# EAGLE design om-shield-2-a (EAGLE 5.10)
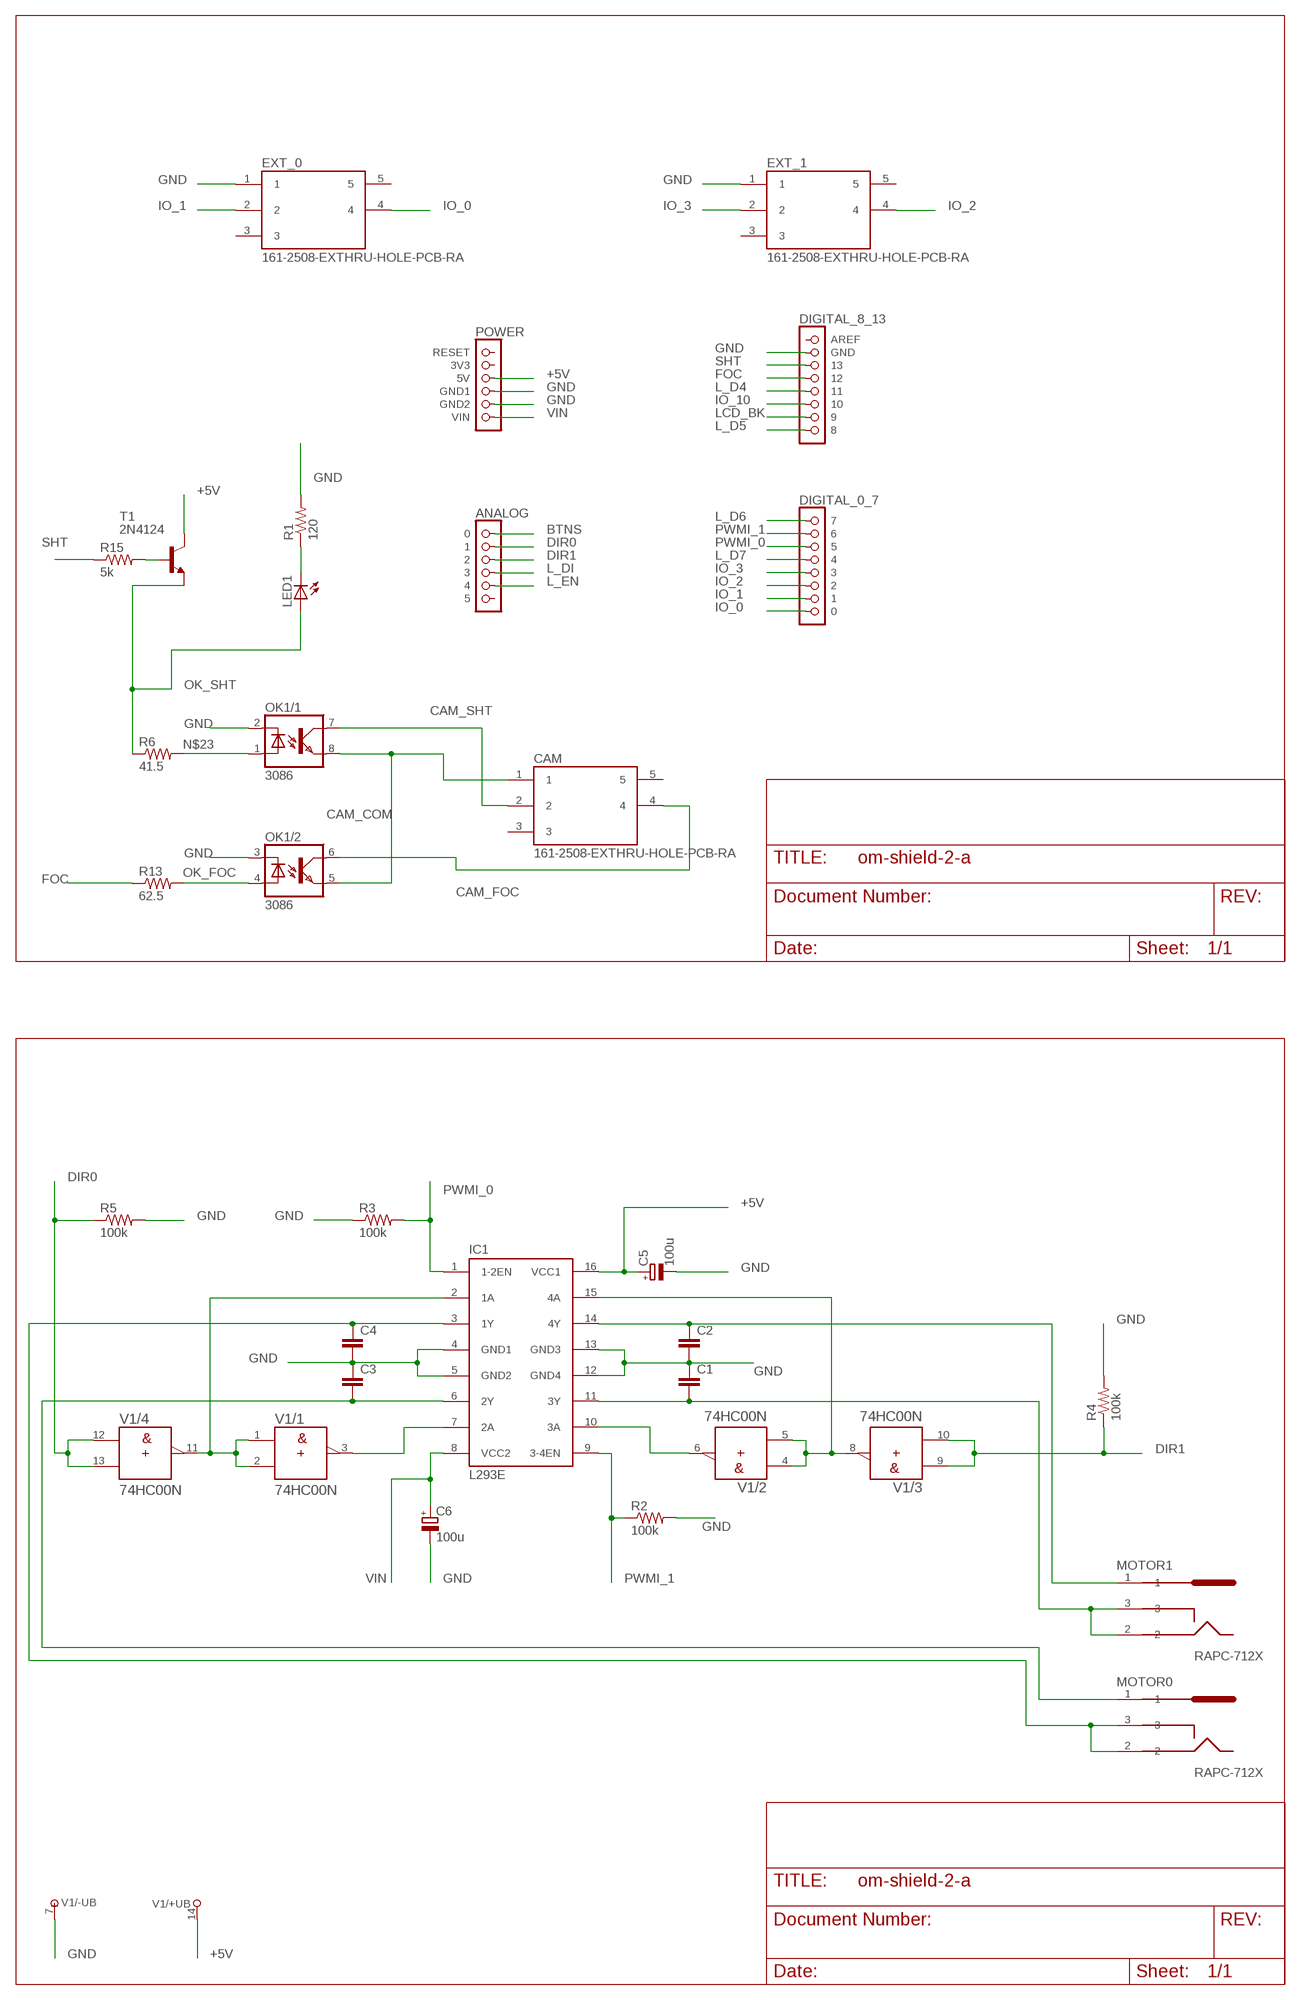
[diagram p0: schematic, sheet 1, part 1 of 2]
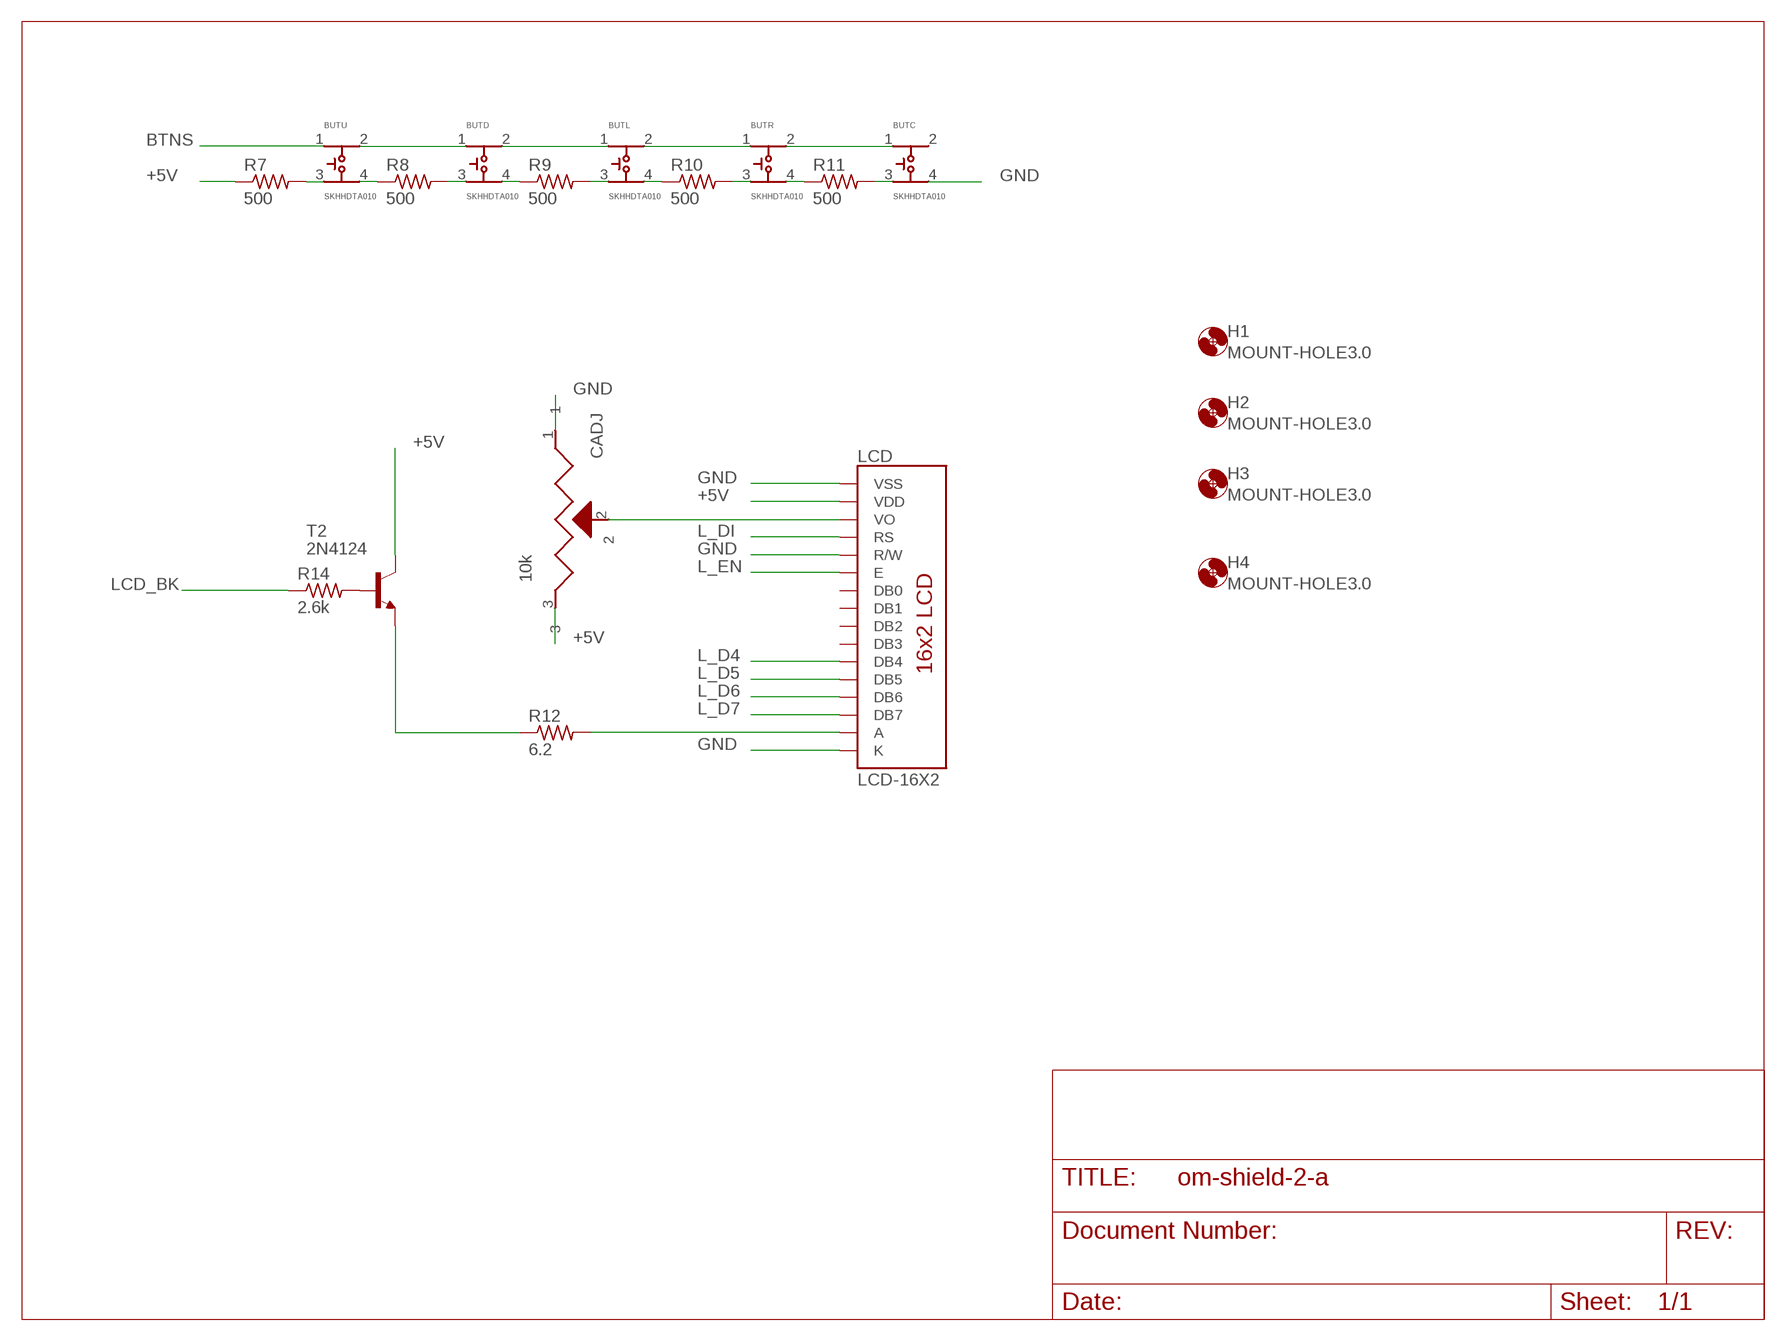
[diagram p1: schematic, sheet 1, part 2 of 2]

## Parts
BUTC  SKHHDTA010  SKHH  [SKHH]
BUTD  SKHHDTA010  SKHH  [SKHH]
BUTL  SKHHDTA010  SKHH  [SKHH]
BUTR  SKHHDTA010  SKHH  [SKHH]
BUTU  SKHHDTA010  SKHH  [SKHH]
C1  C5/3  [C5B3]
C2  C5/3  [C5B3]
C3  C5/3  [C5B3]
C4  C5/3  [C5B3]
C5  100u  CPOL-EUE2-5  [E2-5]
C6  100u  CPOL-EUE2-5  [E2-5]
CADJ  10k  3362U  [3362W]
CAM  161-2508-EXTHRU-HOLE-PCB-RA  [PCB-HORIZ]
EXT_0  161-2508-EXTHRU-HOLE-PCB-RA  [PCB-HORIZ]
EXT_1  161-2508-EXTHRU-HOLE-PCB-RA  [PCB-HORIZ]
H1  MOUNT-HOLE3.0  [3,0]
H2  MOUNT-HOLE3.0  [3,0]
H3  MOUNT-HOLE3.0  [3,0]
H4  MOUNT-HOLE3.0  [3,0]
IC1  L293E  [DIL16]
LCD  LCD-16X2  [LCD-16X2]
LED1  LED3MM  [LED3MM]
MOTOR0  RAPC-712X  [RAPC712X]
MOTOR1  RAPC-712X  [RAPC712X]
OK1  3086  [DIL08]
R1  120  R-US_0207/7  [0207/7]
R2  100k  R-US_0207/7  [0207/7]
R3  100k  R-US_0207/7  [0207/7]
R4  100k  R-US_0207/7  [0207/7]
R5  100k  R-US_0207/7  [0207/7]
R6  41.5  R-US_0207/7  [0207/7]
R7  500  R-US_0207/7  [0207/7]
R8  500  R-US_0207/7  [0207/7]
R9  500  R-US_0207/7  [0207/7]
R10  500  R-US_0207/7  [0207/7]
R11  500  R-US_0207/7  [0207/7]
R12  6.2  R-US_0207/7  [0207/7]
R13  62.5  R-US_0207/7  [0207/7]
R14  2.6k  R-US_0207/7  [0207/7]
R15  5k  R-US_0207/7  [0207/7]
T1  2N4124  2N4124-NPN-TO92-CBE  [TO92-CBE]
T2  2N4124  2N4124-NPN-TO92-CBE  [TO92-CBE]
U$1  POWER  [1X06]
U$2  ANALOG  [1X06]
U$3  DIGITAL_0_7  [1X08]
U$4  DIGITAL_8_13  [1X08]
V1  74HC00N  [DIL14]

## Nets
+5V: C5.+ CADJ.3 IC1.16(VCC1) LCD.2(VDD) R7.1 T1.C T2.C U$1.3(5V) V1.14(/+UB:+UB)
BTNS: BUTU.1 U$2.1
CAM_COM: CAM.1 OK1.5(/2:EMI) OK1.8(/1:EMI)
CAM_FOC: CAM.4 OK1.6(/2:COL)
CAM_SHT: CAM.2 OK1.7(/1:COL)
DIR0: R5.1 U$2.2 V1.12(/4:A) V1.13(/4:B)
DIR1: R4.1 U$2.3 V1.9(/3:A) V1.10(/3:B)
FOC: R13.1 U$4.4
GND: BUTC.4 C1.1 C2.2 C3.1 C4.2 C5.- C6.- CADJ.1 EXT_0.1 EXT_1.1 IC1.4(GND1) IC1.5(GND2) IC1.12(GND4) IC1.13(GND3) LCD.1(VSS) LCD.5(R/W) LCD.16(K) OK1.2(/1:C) OK1.3(/2:C) R1.2 R2.2 R3.1 R4.2 R5.2 U$1.4(GND1) U$1.5(GND2) U$4.2(GND) V1.7(/-UB:-UB)
IO_0: EXT_0.4 U$3.8
IO_1: EXT_0.2 U$3.7
IO_2: EXT_1.4 U$3.6
IO_3: EXT_1.2 U$3.5
IO_10: U$4.6
L_D4: LCD.11(DB4) U$4.5
L_D5: LCD.12(DB5) U$4.8
L_D6: LCD.13(DB6) U$3.1
L_D7: LCD.14(DB7) U$3.4
L_DI: LCD.4(RS) U$2.4
L_EN: LCD.6(E) U$2.5
LCD_BK: R14.1 U$4.7
LCDA: LCD.15(A) R12.2
M0_A: C3.2 IC1.6(2Y) MOTOR0.1
M0_B: C4.1 IC1.3(1Y) MOTOR0.2 MOTOR0.3
M1_A: C2.1 IC1.14(4Y) MOTOR1.1
M1_B: C1.2 IC1.11(3Y) MOTOR1.2 MOTOR1.3
N$1: LED1.K(C) R1.1
N$2: IC1.7(2A) V1.3(/1:Y)
N$3: IC1.2(1A) V1.1(/1:A) V1.2(/1:B) V1.11(/4:Y)
N$4: IC1.10(3A) V1.6(/2:Y)
N$5: IC1.15(4A) V1.4(/2:A) V1.5(/2:B) V1.8(/3:Y)
N$8: BUTU.3 R7.2
N$9: BUTU.4 R8.1
N$10: BUTD.3 R8.2
N$11: BUTD.4 R9.1
N$12: BUTL.3 R9.2
N$13: BUTL.4 R10.1
N$14: BUTR.3 R10.2
N$15: BUTR.4 R11.1
N$16: BUTC.3 R11.2
N$17: BUTD.1 BUTU.2
N$18: BUTD.2 BUTL.1
N$19: BUTL.2 BUTR.1
N$20: BUTC.1 BUTR.2
N$21: CADJ.2 LCD.3(VO)
N$23: OK1.1(/1:A) R6.2
N$24: R12.1 T2.E
N$25: R15.2 T1.B
N$26: R14.2 T2.B
OK_FOC: OK1.4(/2:A) R13.2
OK_SHT: LED1.A R6.1 T1.E
PWMI_0: IC1.1(1-2EN) R3.2 U$3.3
PWMI_1: IC1.9(3-4EN) R2.1 U$3.2
SHT: R15.1 U$4.3
VIN: C6.+ IC1.8(VCC2) U$1.6(VIN)
Unconnected: BUTC.2 CAM.3 CAM.5 EXT_0.3 EXT_0.5 EXT_1.3 EXT_1.5 LCD.7(DB0) LCD.8(DB1) LCD.9(DB2) LCD.10(DB3) U$1.1(RESET) U$1.2(3V3) U$2.6 U$4.1(AREF)

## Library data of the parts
BUTC BUTD BUTL BUTR BUTU = alps:SKHH: SKHH* vertical/joint stem momentary pushbutton PCB mount switch
C1-C4 = capacitor-wima:C: CAPACITOR
C5 C6 = rcl:CPOL-EU: POLARIZED CAPACITOR, European symbol
CADJ = bourns:3362U: Bourns 3362U trim pot top-adjust.
CAM EXT_0 EXT_1 = kobiconn-161-2508-ex:161-2508-EX
H1-H4 = holes:MOUNT-HOLE: MOUNTING HOLE with drill center marker
IC1 = texas:L293E: TI DEVICE
LCD = SparkFun:LCD-16X2
LED1 = SparkFun:LED: LEDs
MOTOR0 MOTOR1 = switchcraft:RAPC-712X
OK1 = cchurch-optocoupler:3086: NTE3086 Dual Opto-Coupler DIL8
R1-R15 = resistor:R-US_: RESISTOR, American symbol
T1 T2 = transistor:*-NPN-: NPN Transistror BF959 corrected 2008.03.06
U$1 = arduino:POWER
U$2 = arduino:ANALOG
U$3 = arduino:DIGITAL_0_7
U$4 = arduino:DIGITAL_8_13
V1 = 74ttl-din:74*00: Quad 2-input NAND gate

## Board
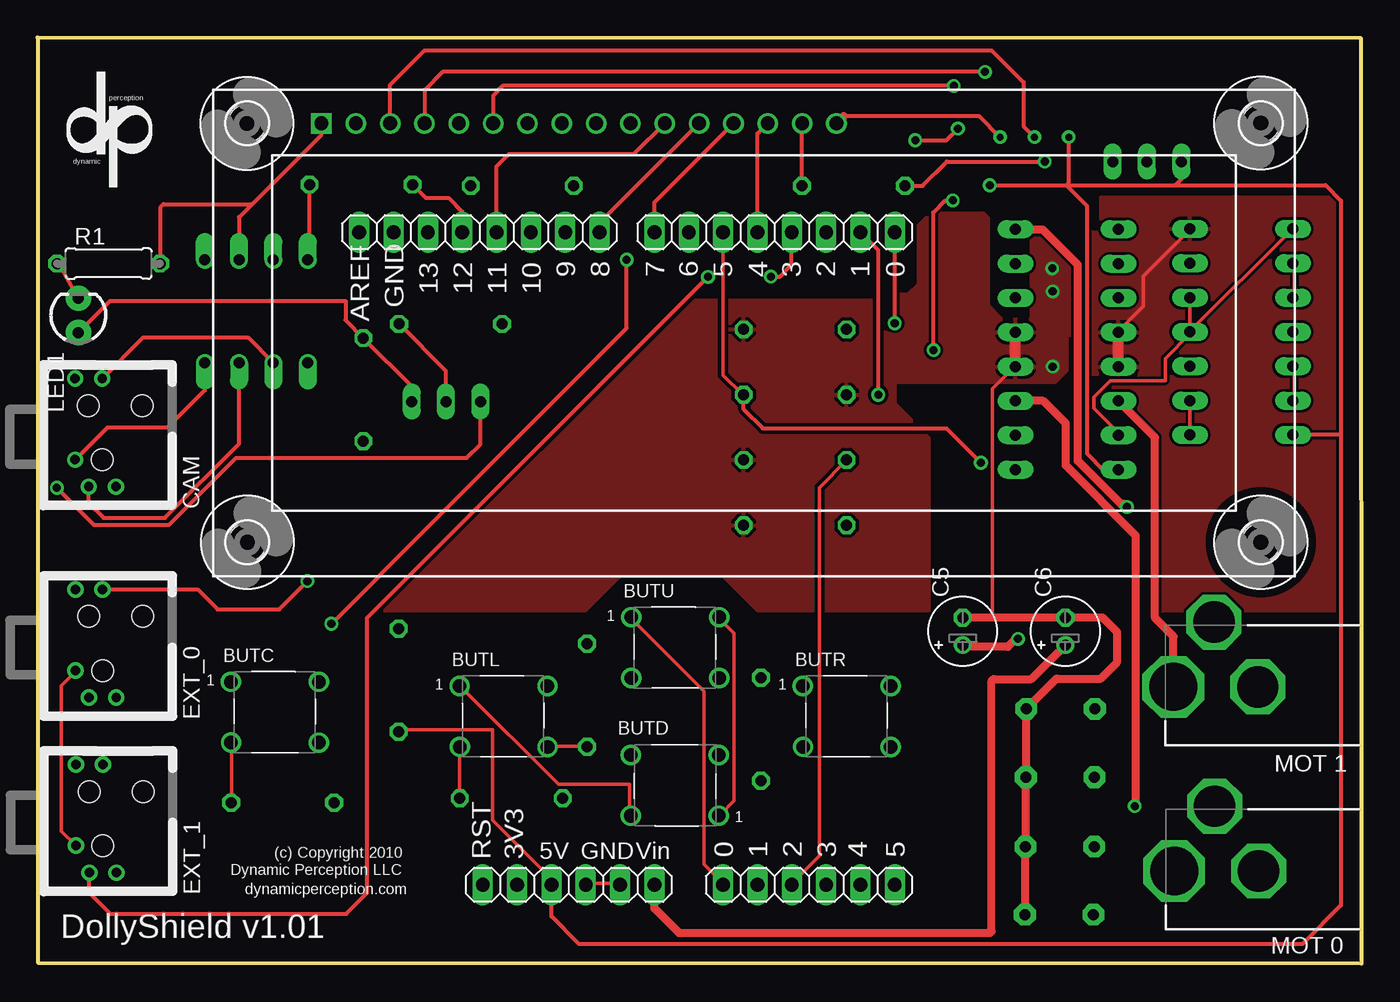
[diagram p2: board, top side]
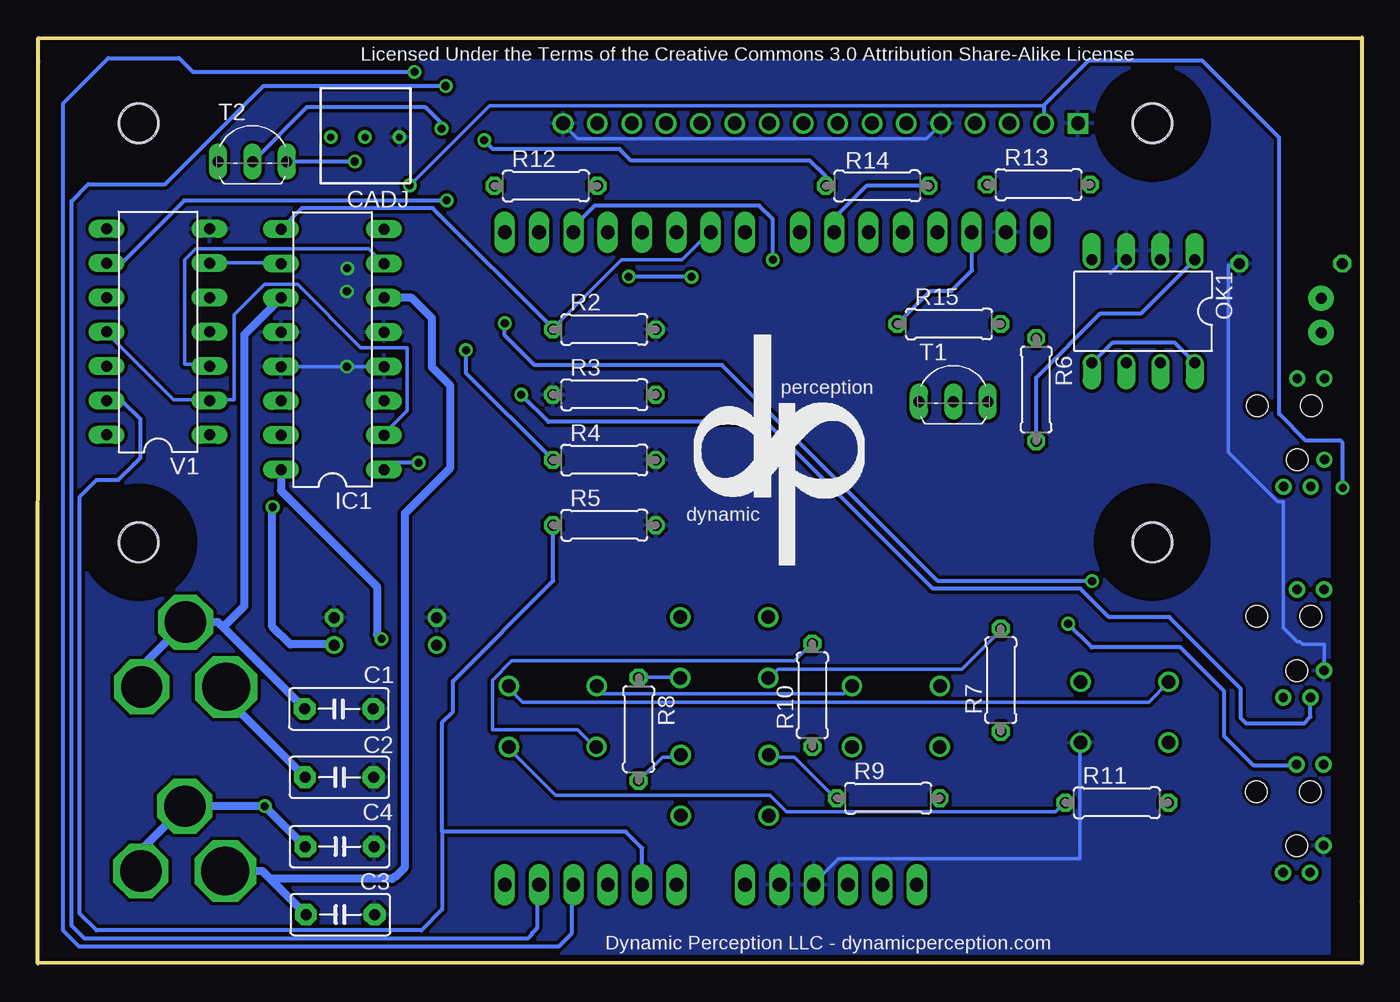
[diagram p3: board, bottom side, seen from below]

Size 98.04 x 68.48 mm. Coordinates in mm from the lower left corner, seen from the top.
Outline: 0,3.28 0,56.62
Outline: 0.08,68.48 0.1,0.05 98.04,0 98.02,68.43 0.08,68.48
Copper layers (1*16): Top 0.035mm / dielectric 1.5mm / Bottom 0.035mm
Design rules "default *": minimum track width 10mil, minimum drill 24mil, track to track 8mil, track to pad 8mil, pad to pad 8mil, via to via 8mil, smd to smd 8mil, copper to edge 10mil, drill to drill 8mil, minimum pad ring 10mil, minimum via ring 8mil, stop-mask expansion 4mil, vias tented up to drill 0mil, thermal gap 10mil

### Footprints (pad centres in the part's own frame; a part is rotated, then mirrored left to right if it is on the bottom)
SKHH = drill 1 round: 1 -3.242,2.261; 2 3.264,2.262; 3 -3.23,-2.242; 4 3.267,-2.245
C5B3 = drill 0.813 pad 1.6 octagon: 1 -2.54,0; 2 2.54,0
E2-5 = drill 0.813 pad 1.27 round: + -1.016,0 | drill 0.813 pad 1.27 octagon: - 1.016,0
3362W = drill 0.5 round: 1 -2.565,0.076; 2 -0.025,0.076; 3 2.515,0.076
PCB-HORIZ = drill 0.7 round: 1 -1.96,-0.32; 2 -3.96,-1.32; 3 -3.96,-3.33; 4 4.04,-2.32; 5 4.04,-0.32 | hole 1.6: 2.04,-1.29; 2.04,-5.29; -1.96,-2.32
3,0 = hole 3: 0,0
DIL16 = drill 0.813 long: 1 -8.89,-3.81; 2 -6.35,-3.81; 3 -3.81,-3.81; 4 -1.27,-3.81; 5 1.27,-3.81; 6 3.81,-3.81; 7 6.35,-3.81; 8 8.89,-3.81; 9 8.89,3.81; 10 6.35,3.81; 11 3.81,3.81; 12 1.27,3.81; 13 -1.27,3.81; 14 -3.81,3.81; 15 -6.35,3.81; 16 -8.89,3.81
LCD-16X2 = drill 1.016 square: 1 -32,15.5 | drill 1.016 round: 2 -29.46,15.5; 3 -26.92,15.5; 4 -24.38,15.5; 5 -21.84,15.5; 6 -19.3,15.5; 7 -16.76,15.5; 8 -14.22,15.5; 9 -11.68,15.5; 10 -9.14,15.5; 11 -6.6,15.5; 12 -4.06,15.5; 13 -1.52,15.5; 14 1.02,15.5; 15 3.56,15.5; 16 6.1,15.5 | hole 2.8: -37.5,15.5; -37.5,-15.5; 37.5,15.5; 37.5,-15.5
LED3MM = drill 0.813 pad 1.88 round: A -1.27,0; K 1.27,0
RAPC712X = drill 3.556 octagon: 1 0,-6.248 | drill 3.048 octagon: 2 0,0; 3 -4.801,-3.251
DIL08 = drill 0.813 offset: 1 -3.81,-3.81; 2 -1.27,-3.81; 3 1.27,-3.81; 4 3.81,-3.81; 5 3.81,3.81; 6 1.27,3.81; 7 -1.27,3.81; 8 -3.81,3.81
0207/7 = drill 0.813 octagon: 1 -3.81,0; 2 3.81,0
TO92-CBE = drill 0.813 long: B 0,0; C -2.54,0; E 2.54,0
1X06 = drill 1.016 long: 1 -6.35,0; 2 -3.81,0; 3 -1.27,0; 4 1.27,0; 5 3.81,0; 6 6.35,0
1X08 = drill 1.016 long: 1 -8.89,0; 2 -6.35,0; 3 -3.81,0; 4 -1.27,0; 5 1.27,0; 6 3.81,0; 7 6.35,0; 8 8.89,0
DIL14 = drill 0.813 long: 1 -7.62,-3.81; 2 -5.08,-3.81; 3 -2.54,-3.81; 4 0,-3.81; 5 2.54,-3.81; 6 5.08,-3.81; 7 7.62,-3.81; 8 7.62,3.81; 9 5.08,3.81; 10 2.54,3.81; 11 0,3.81; 12 -2.54,3.81; 13 -5.08,3.81; 14 -7.62,3.81

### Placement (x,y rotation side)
BUTC  17.63,18.57 0 top
BUTD  47.24,13.18 180 top
BUTL  34.54,18.26 0 top
BUTR  59.94,18.26 0 top
BUTU  47.24,23.34 0 top
C1  75.77,18.82 180 bottom
C2  75.74,13.77 0 bottom
C3  75.67,3.61 180 bottom
C4  75.72,8.64 0 bottom
C5  68.53,24.56 90 top
C6  76.12,24.56 90 top
CADJ  73.86,61.19 180 bottom
CAM  2.54,39.22 90 top
EXT_0  2.57,23.62 90 top
EXT_1  2.59,10.67 90 top
H1  15.57,62.13 0 top
H2  90.58,62.15 0 top
H3  15.6,31.14 0 top
H4  90.58,31.14 0 top
IC1  76.25,45.42 90 bottom
LCD  53.09,46.63 0 top
LED1  3.1,47.93 90 top
MOTOR0  90.42,6.83 270 top
MOTOR1  90.37,20.45 270 top
OK1  16.26,48.23 180 bottom
R1  5.33,51.77 0 top
R2  56.13,46.89 0 bottom
R3  56.13,42.06 0 bottom
R4  56.13,37.24 0 bottom
R5  56.13,32.41 0 bottom
R6  24.18,42.44 270 bottom
R7  26.8,20.95 90 bottom
R8  53.59,17.32 270 bottom
R9  35.13,12.22 0 bottom
R10  40.74,19.84 90 bottom
R11  18.21,11.89 0 bottom
R12  60.45,57.51 0 bottom
R13  24,57.61 0 bottom
R14  35.94,57.51 180 bottom
R15  30.63,47.29 0 bottom
T1  30.3,41.55 0 bottom
T2  82.17,59.31 0 bottom
U$1  39.37,5.82 0 top
U$2  57.15,5.82 0 top
U$3  54.61,54.08 0 top
U$4  32.77,54.08 0 top
V1  89.15,46.71 90 bottom

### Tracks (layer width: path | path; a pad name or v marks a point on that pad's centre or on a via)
+5V  (via drill 0.6)
  Top 0.254: R7.1 26.82,17.3 33.73,17.3 33.73,10.59 38,6.32 38,5.92 U$1.3
  Top 0.305: 84.25,57.56 95.38,57.56 96.52,56.41 96.52,39.09 | 76.2,57.56 84.25,57.56 | v70.54,57.56 76.2,57.56 | U$1.3 38.1,3.48 40.16,1.42 93.65,1.42 96.52,4.29 96.52,39.09 | CADJ.3 76.38,57.73 76.2,57.56 | T2.C 84.71,58.01 84.25,57.56 | 96.52,39.09 V1.14 | IC1.16 78.92,36.53 77.72,37.72 77.72,56.03 76.2,57.56 | T1.C 32.84,38.4 31.83,37.39 14.76,37.39 9.8,32.44 4.24,32.44 v1.5,35.18
  Top 0.61: C5.+ 68.66,23.42 71.88,23.42 72.47,24 v72.62,24
  Bottom 0.254: 70.31,57.73 64.62,63.42 23.77,63.42 23.63,63.47
  Bottom 0.305: LCD.2 23.63,63.47 20.32,66.78 11.89,66.78 6.2,61.09 6.2,40.64 4.22,38.66 1.65,38.66 1.5,38.51 1.5,36.3 v1.5,35.18 | v70.54,57.56 70.48,57.56 70.31,57.73
  Bottom 0.61: v72.62,24 72.95,24.33 72.95,27.86 80.06,34.98 IC1.16
BTNS
  Top 0.254: BUTU.1 44.09,25.43 49.38,20.14 49.38,7.34 50.8,5.92 U$2.1
CAM_COM
  Top 0.305: CAM.1 5.25,39.65 9.7,39.65 12.45,42.39 OK1.8
  Bottom 0.305: OK1.8 13.92,45.9 18.54,45.9 20.02,44.42 OK1.5
CAM_FOC
  Top 0.305: CAM.4 7.91,46.3 15.65,46.3 OK1.6
CAM_SHT
  Top 0.305: CAM.2 3.86,34.04 4.95,32.94 9.5,32.94 14.99,38.43 OK1.7
DIR0
  Top 0.254: V1.13 93.07,41.68 93.07,44.12 V1.12
  Bottom 0.305: V1.13 91.85,41.63 90.45,40.23 90.45,37.39 90.91,36.93 90.93,36.93 92.1,35.76 93.7,35.76 94.94,34.52 94.94,3.68 93.7,2.44 69.67,2.44 68.12,3.99 68.12,9.75 | 68.12,9.75 68.12,17.83 67.33,18.62 67.33,20.88 59.92,28.3 59.92,32.38 R5.1 | U$2.2 53.34,8.53 54.56,9.75 68.12,9.75
DIR1  (via drill 0.6)
  Top 0.254: V1.10 93.07,49.4 93.07,51.64 V1.9 | R4.1 59.94,37.21 57.91,35.18 57.91,7.95 55.88,5.92 U$2.3
  Top 0.305: v66.37,45.36 66.34,45.39 66.34,55.52 67.26,56.44 v67.79,56.44
  Bottom 0.305: R4.1 66.37,43.66 v66.37,45.36 | v67.79,56.44 67.82,56.41 87.22,56.41 91.85,51.79 V1.9
FOC
  Top 0.305: U$4.4 31.5,55.6 30.48,56.62 28.8,56.62 R13.1
GND  (via drill 0.6)
  Top 0.254: U$1.5 43.08,5.92 40.64,5.92 U$1.4 | 72.54,44.32 IC1.4 72.34,44.12 70.71,42.49 70.71,25.58 | 72.54,46.56 IC1.5 72.34,46.76 | V1.7 85.34,54.28 81.89,50.83 81.89,48.59 80.06,46.76 IC1.12 | EXT_0.1 2.85,21.56 1.83,20.55 1.83,9.78 2.85,8.76 EXT_1.1
  Top 0.305: R1.2 9.2,51.82 9.2,55.98 9.37,56.16 15.95,56.16 | OK1.2 14.99,55.19 15.95,56.16 | 15.95,56.16 21.09,61.29 LCD.1 | 59.74,62.69 69.72,62.69 CADJ.1
  Top 0.61: C3.1 73.18,3.66 C4.2 73.2,8.66 C2.2 73.23,13.79 C1.1 75.46,21.06 78.74,21.06 79.96,22.28 79.96,24.51 78.89,25.58 C6.- 70.71,25.58 C5.- | LCD.16 59.74,62.69
  Top 0.813: 72.54,44.32 72.44,44.42 IC1.5 | IC1.13 IC1.12
  Bottom 0.254: BUTC.4 20.93,16.28 20.93,7.75 38.81,7.75 40.64,5.92 U$1.4 | IC1.4 72.54,44.12 80.06,44.12 IC1.13 | LCD.5 31.29,62 32.31,60.99 58.12,60.99 59.13,62 LCD.16 | EXT_0.1 2.85,21.77 2.85,23.6 4.47,23.6 4.67,23.8 4.88,23.8 5.89,24.82 5.89,34.16 6.3,34.16 9.96,37.82 9.96,51.64 9.14,51.64 R1.2 | 18.69,51.03 17.68,52.04 OK1.3
  other vias: 75.16,51.41 75.18,49.71 75.18,44.15
  pour Top: 78.13,47.88 83.16,47.88 83.16,43.59 78.13,43.59
  pour Top: 76.2,49 76.2,43.92 76.2,43.84 75.36,43 63.73,43 63.07,43.66 63.07,49.4 63.14,49.48 64.52,49.48 65.28,50.24 65.28,54.58 66.19,55.5 70.05,55.5 70.38,55.17 70.38,48.67 71.4,47.65 74.85,47.65
  pour Bottom (isolate 0.254): 2.54,66.78 2.54,0.74 96.52,0.74 96.52,66.78
  pour Top (isolate 0.254): 63.5,49 27.94,49 22.86,43.92 22.86,26.14 40.64,26.14 43.18,28.68 50.8,28.68 53.34,26.14 66.04,26.14 66.04,38.84 63.5,41.38
  pour Top: 78.74,56.62 78.74,26.14 96.52,26.14 96.52,56.62
  pour Top: 73.66,46.46 73.66,54.08 78.74,54.08 78.74,46.46
IO_0  (via drill 0.6)
  Top 0.305: EXT_0.4 11.91,27.66 13.39,26.19 17.96,26.19 v20.04,28.27 | v63.5,47.35 U$3.8
  Bottom 0.305: v20.04,28.27 31.45,28.27 47.42,44.25 61.29,44.25 63.5,46.46 v63.5,47.35
IO_1  (via drill 0.6)
  Top 0.305: v62.28,42.06 62.28,52.76 U$3.7
  Bottom 0.305: EXT_0.2 3.88,18.24 4.39,17.73 8.64,17.73 9.04,18.14 9.04,20.32 14.33,25.6 18.8,25.6 20.9,27.71 31.83,27.71 44.17,40.06 60.27,40.06 v62.28,42.06
IO_2  (via drill 0.6)
  Top 0.305: v21.82,25.12 25.38,28.68 25.38,28.7 43.66,46.99 v43.66,52.04
  Bottom 0.305: v21.82,25.12 20.07,23.37 13.51,23.37 10.26,20.12 10.26,16.81 8.08,14.63 4.99,14.63 EXT_1.4 | v43.66,52.04 43.66,55.04 44.68,56.06 56.84,56.06 58.45,54.46 58.45,54.1 U$3.6
IO_3  (via drill 0.6)
  Top 0.305: EXT_1.2 3.91,5.21 5.46,3.66 22.91,3.66 24.46,5.21 24.46,25.55 v49.68,50.77 | v54.33,50.8 54.99,50.8 55.85,51.66 55.85,54.05 U$3.5
  Bottom 0.305: v49.68,50.77 54.3,50.77 v54.33,50.8
L_D4
  Top 0.305: U$4.5 34.04,58.95 34.95,59.87 44.22,59.87 LCD.11
L_D5
  Top 0.305: LCD.12 41.66,54.76 U$4.8
L_D6
  Top 0.305: LCD.13 45.72,56.29 U$3.1
L_D7
  Top 0.305: LCD.14 53.34,61.37 U$3.4
L_DI  (via drill 0.6)
  Top 0.305: LCD.4 28.71,64.6 30.05,65.94 v70.18,65.94
  Bottom 0.305: U$2.4 58.57,5.66 58.57,2.18 59.51,1.24 95,1.24 96.16,2.41 96.16,63.63 92.84,66.95 87.61,66.95 86.59,65.94 v70.18,65.94
L_EN  (via drill 0.6)
  Top 0.305: LCD.6 33.79,64.21 33.78,64.21 33.81,64.21 34.49,64.9 v67.87,64.9
  Bottom 0.305: U$2.5 61.11,5.66 61.11,2.62 61.49,2.24 61.49,2.16 61.82,1.83 94.59,1.83 95.56,2.79 95.56,56.39 94.31,57.63 88.62,57.63 81.36,64.9 v67.87,64.9
LCD_BK
  Bottom 0.305: U$4.7 39.12,55.14 36.75,57.51 R14.1
LCDA
  Top 0.305: R12.2 LCD.15
M0_A
  Bottom 0.61: 80.85,6.25 C3.2 | MOTOR0.1 81.43,6.83 80.85,6.25 | 80.85,6.25 71.83,6.25 71.7,6.38 71.63,6.38 70.89,7.11 70.89,33.3 67.51,36.68 67.51,42.72 68.89,44.09 68.89,47.73 70.38,49.23 IC1.6
M0_B  (via drill 0.6)
  Top 0.61: v81.25,11.63 81.33,11.71 81.33,31.65 76.15,36.83 76.15,39.95 74.5,41.61 IC1.3
  Bottom 0.61: C4.1 v81.25,11.63 MOTOR0.3 90.42,8.38 MOTOR0.2
M1_A
  Top 0.61: IC1.14 82.75,38.91 82.75,25.55 84.12,24.18 MOTOR1.1
  Bottom 0.61: C2.1 84.12,19.61 MOTOR1.1
M1_B
  Bottom 0.61: C1.2 84.53,25.04 | 84.53,25.04 84.73,25.25 MOTOR1.3 90.37,22 MOTOR1.2 | IC1.11 82.75,46.53 82.75,26.44 84.15,25.04 84.53,25.04
N$1
  Top 0.305: R1.1 1.83,51.46 LED1.K
N$2
  Bottom 0.254: IC1.7 72.54,51.84 73.56,52.86 86.36,52.86 87.17,52.04 87.17,44.32 85.34,44.32 V1.3
N$3
  Top 0.254: V1.2 V1.1
  Bottom 0.254: 85.34,41.68 83.52,41.68 83.52,47.98 81.28,50.22 78.84,50.22 74.17,45.54 70.71,45.54 70.71,40.87 72.34,39.24 IC1.2 | 85.34,41.68 87.99,41.68 92.86,46.56 V1.11 | 85.34,41.68 V1.2
N$4
  Bottom 0.254: IC1.10 80.06,51.84 85.34,51.84 V1.6
N$5
  Top 0.254: IC1.15 80.06,39.24 78.23,41.07 78.23,41.88 79.45,43.1 83.52,43.1 83.52,44.73 85.34,46.56 V1.4 85.34,46.76 | 85.34,46.76 V1.5 | 85.34,46.76 92.86,54.28 V1.8
N$6
  Bottom 0.305: 0.1,4.57 0.1,-0.03
N$7
  Bottom 0.305: 98.02,68.45 98.02,66.73 98.04,66.73
N$8
  Bottom 0.254: R7.2 26.82,24.61 29.67,21.77 43.28,21.77 43.89,21.16 BUTU.3
N$9
  Bottom 0.254: R8.1 53.44,21.16 50.6,21.16 BUTU.4
N$10
  Bottom 0.254: R8.2 53.44,13.64 51.82,15.27 50.6,15.27 BUTD.3
N$11
  Bottom 0.254: R9.1 39.01,12.22 42.06,15.27 43.89,15.27 BUTD.4
N$12
  Top 0.254: R9.2 31.29,12.22 31.29,15.87 BUTL.3
N$13
  Top 0.254: R10.1 40.64,16.08 38,16.08 BUTL.4
N$14
  Bottom 0.254: R10.2 40.84,23.6 42.06,22.38 62.99,22.38 64.41,20.95 64.41,17.3 58.12,17.3 56.9,16.08 BUTR.3
N$15
  Bottom 0.254: R11.1 22.15,11.81 22.76,11.2 42.67,11.2 43.89,12.42 59.74,12.42 63.2,15.87 BUTR.4
N$16
  Top 0.254: R11.2 14.43,12.01 14.43,16.28 BUTC.3
N$17
  Top 0.254: BUTD.1 50.6,11 51.61,12.01 51.61,24.41 50.6,25.43 BUTU.2
N$18
  Top 0.254: BUTL.1 31.5,20.35 38.61,13.23 43.89,13.23 43.89,11 BUTD.2
N$19
  Bottom 0.254: BUTR.1 56.69,20.35 56.29,19.94 38.41,19.94 38,20.35 BUTL.2
N$20
  Bottom 0.254: BUTC.1 14.43,20.75 15.85,19.33 62.18,19.33 63.2,20.35 BUTR.2
N$21
  Top 0.305: LCD.3 26.17,65 28.7,67.54 70.66,67.54 73.03,65.18 73.03,61.93 CADJ.2
N$23
  Bottom 0.305: R6.2 24.18,43.33 19.43,48.08 16.41,48.08 OK1.1
N$24  (via drill 0.6)
  Top 0.305: v74.6,59.31 67.36,59.31 65.56,57.51 R12.1
  Bottom 0.305: v74.6,59.31 T2.E
N$25
  Top 0.305: T1.B 30.3,43.81 R15.2
N$26  (via drill 0.6)
  Top 0.305: v65.02,60.88 67.31,60.88 v68.17,61.75
  Bottom 0.305: v65.02,60.88 64.36,60.22 54.99,60.22 54.15,59.39 40.92,59.39 39.75,58.22 R14.2 | v68.17,61.75 68.17,62.13 69.37,63.32 78.16,63.32 T2.B
OK_FOC
  Top 0.305: R13.2 20.19,52.17 OK1.4
OK_SHT
  Top 0.305: LED1.A 5.44,49 22.86,49 22.86,47.57 R6.1 27.76,42.67 T1.E
PWMI_0  (via drill 0.6)
  Top 0.254: U$3.3 50.8,43.51 52.22,42.09 R3.2
  Top 0.305: R3.2 52.32,41 53.75,39.57 67.33,39.57 v69.88,37.03
  Bottom 0.305: v69.88,37.03 71.93,37.03 IC1.1
PWMI_1
  Bottom 0.254: R2.1 59.94,46.96 54.86,52.04 50.39,52.04 48.36,54.08 U$3.2
  Bottom 0.305: 59.94,46.96 68.83,55.85 78.51,55.85 IC1.9
SHT
  Bottom 0.305: U$4.3 28.93,54.05 28.93,51.26 30.48,49.71 32.03,49.71 R15.1
VIN  (via drill 0.61)
  Top 0.61: C6.+ 73.61,21.03 70.81,21.03 70.66,20.88 70.66,2.36 70.56,2.26 47.52,2.26 45.72,4.06 U$1.6 | IC1.8 72.47,54.28 74.45,54.28 77.04,51.69 77.04,37.16 80.21,33.99 80.44,33.99 v80.67,33.76
  Bottom 0.254: C6.+ 76.2,23.6
  Bottom 0.61: 76.2,23.6 79.38,23.6 80.7,24.92 80.7,33.73 v80.67,33.76

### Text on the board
tPlace: perception | dynamic | (c) Copyright 2010 | Dynamic Perception LLC | dynamicperception.com | DollyShield v1.01
bPlace: Licensed Under the Terms of the Creative Commons 3.0 Attribution Share-Alike License | perception | dynamic | Dynamic Perception LLC - dynamicperception.com
tNames: 9 | 8 | 7 | 6 | 5 | 4 | 3 | 2 | 1 | 0 | 13 | 12 | 11 | 10 | GND | AREF | MOT 1 | 0 | 1 | 2 | 3 | 4 | 5 | RST | 3V3 | 5V | GND | Vin | MOT 0
TallParts: USB | ISP | PWR
ArduinoHoles: 3.2mm | 2.2mm | 3.2mm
